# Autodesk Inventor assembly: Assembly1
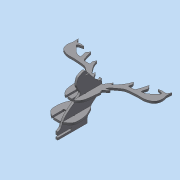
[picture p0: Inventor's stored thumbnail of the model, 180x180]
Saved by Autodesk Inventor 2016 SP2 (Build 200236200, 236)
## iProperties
Created: 2017-07
Part Number: Assembly1
Document SubType Name: Assembly
Designer: Mohamed A.
Author: Mohamed A.
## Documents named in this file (4)
- C:\Users\Mohamed\Documents\inventor\cam\Assembly1.iam
- C:\Users\Mohamed\Documents\inventor\cam\Part1.ipt
- C:\Users\Mohamed\Documents\inventor\cam\Part2.ipt
- C:\Users\Mohamed\Documents\inventor\cam\Part3.ipt
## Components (3 placed, 3 different names)
1. Part1:1 — Mate:1, Mate:2, Mate:3
2. Part2:1 — Mate:4, Mate:5, Mate:6
3. Part3:1 — Mate:1, Mate:2, Mate:3, Mate:4, Mate:5, Mate:6
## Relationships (6: Mate 6)
- Mate:1: Part1:1 ↔ Part3:1
- Mate:2: Part1:1 ↔ Part3:1
- Mate:3: Part1:1 ↔ Part3:1
- Mate:4: Part2:1 ↔ Part3:1
- Mate:5: Part2:1 ↔ Part3:1
- Mate:6: Part2:1 ↔ Part3:1
